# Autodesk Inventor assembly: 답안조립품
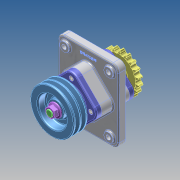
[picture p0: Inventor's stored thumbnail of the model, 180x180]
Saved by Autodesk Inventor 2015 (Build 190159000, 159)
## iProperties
Created: 2026-07
Part Number: 답안조립품
Document SubType Name: Assembly
Designer: USER
Author: USER
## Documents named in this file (12)
- C:\Users\USER\Desktop\760705V1007\답안조립품.iam
- C:\Users\USER\Desktop\760705V1007\본체.ipt
- C:\Users\USER\Desktop\760705V1007\가져온 구성요소\6각 구멍붙이 볼트 M6x16\6각 구멍붙이 볼트 M6x16.ipt
- C:\Users\USER\Desktop\760705V1007\가져온 구성요소\6각 플랜지 너트 M16\6각 플랜지 너트 M16.ipt
- C:\Users\USER\Desktop\760705V1007\가져온 구성요소\V-벨트풀리\V-벨트풀리.ipt
- C:\Users\USER\Desktop\760705V1007\가져온 구성요소\깊은 홈 볼 베어링 6206\깊은 홈 볼 베어링 6206.ipt
- C:\Users\USER\Desktop\760705V1007\가져온 구성요소\오일 실 30 45 8\오일 실 30 45 8.ipt
- C:\Users\USER\Desktop\760705V1007\가져온 구성요소\체인 스프로킷\체인 스프로킷.ipt
- C:\Users\USER\Desktop\760705V1007\가져온 구성요소\축\축.ipt
- C:\Users\USER\Desktop\760705V1007\가져온 구성요소\칼라\칼라.ipt
- C:\Users\USER\Desktop\760705V1007\가져온 구성요소\커버\커버.ipt
- C:\Users\USER\Desktop\760705V1007\가져온 구성요소\평행 키 6x6x20\평행 키 6x6x20.ipt
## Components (11 placed, 3 different names)
1. 6각 구멍붙이 볼트 M6x16:1
2. 6각 플랜지 너트 M16:1
3. V-벨트풀리:1
4. 6각 플랜지 너트 M16:2
5. 6각 구멍붙이 볼트 M6x16:2
6. 6각 구멍붙이 볼트 M6x16:3
7. 6각 구멍붙이 볼트 M6x16:4
8. 6각 구멍붙이 볼트 M6x16:5
9. 6각 구멍붙이 볼트 M6x16:6
10. 6각 구멍붙이 볼트 M6x16:7
11. 6각 구멍붙이 볼트 M6x16:8
